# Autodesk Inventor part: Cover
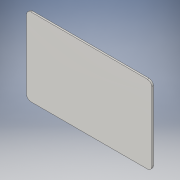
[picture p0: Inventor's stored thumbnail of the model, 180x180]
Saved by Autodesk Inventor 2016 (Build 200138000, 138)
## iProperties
Created: 2015-09
Part Number: Cover
Material: Generic
Document SubType Name: Modeling
Designer: ChombaW
Density: 1 g/cm^3
Appearance: White
Author: ChombaW
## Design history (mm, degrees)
sketch "Sketch1"
  geometry: L1 (93.98, -58.42)-(-93.98, -58.42); L2 (-93.98, -58.42)-(-93.98, 58.42); L3 (-93.98, 58.42)-(93.98, 58.42); L4 (93.98, 58.42)-(93.98, -58.42); L5 (93.98, -58.42)-(-93.98, 58.42); L6 (-93.98, -58.42)-(93.98, 58.42); 1 further point
  constraints: 12 end point, 2 midpoint, 2 parallel, 1 horizontal, 1 perpendicular
  dimensions: "d0" = 187.96 distance of L2.end L3.end; "d1" = 116.84 distance of L1.end L2.end
extrude "Extrusion1" new body sketch "Sketch1" distance "d2" = 2.54; taper "d3" = 0 deg
fillet "Fillet1" dims "d247" = 6.35
fillet "Fillet2" dims "d248" = 6.35
fillet "Fillet3" dims "d249" = 6.35
fillet "Fillet4" dims "d250" = 6.35
body "Solid1"
